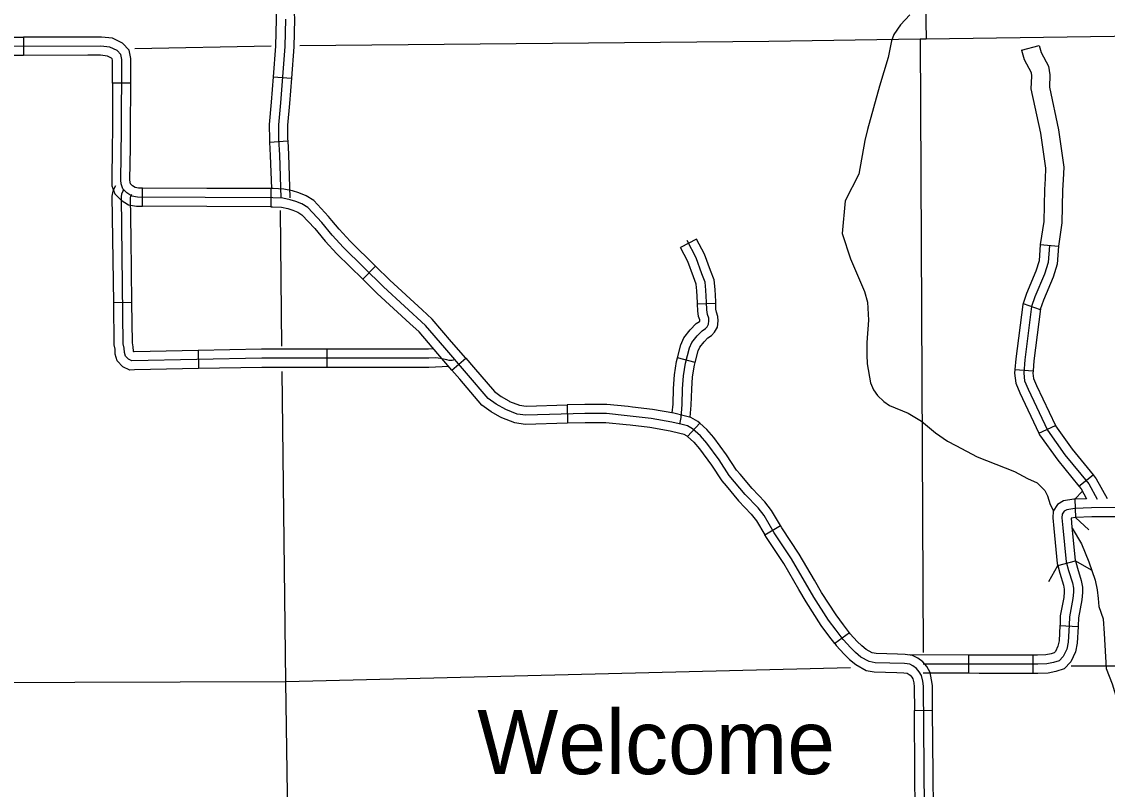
# Model space of a CAD drawing. Extents: x 1373862 to 1376999, y 1168398 to 1170455.
# Drawn here: x 1375095.6 to 1375274.1, y 1169300.7 to 1169426.9 of the extents above; entities that cross this region are included whole.
import ezdxf

# ---------------------------------------------------------------- set-up
doc = ezdxf.new("R2010")
doc.units = 0
for name, color, linetype in [('Level 24', 7, 'Continuous'), ('Level 31', 7, 'Continuous'), ('Level 32', 7, 'Continuous'), ('Level 35', 7, 'Continuous'), ('Level 38', 7, 'Continuous'), ('Level 4', 7, 'Continuous'), ('Level 45', 7, 'Continuous'), ('Level 46', 7, 'Continuous'), ('Level 5', 7, 'Continuous'), ('Level 8', 7, 'Continuous')]:
    doc.layers.add(name, color=color, linetype=linetype)

msp = doc.modelspace()

# ---------------------------------------------------------------- linework, layer by layer
at = {"layer": 'Level 31'}
for p, q in [((1375095.86, 1169424.33), (1375095.87, 1169421.33)), ((1375113.49, 1169416.76), (1375110.49, 1169416.77)), ((1375115.42, 1169396.52), (1375115.43, 1169399.52)), ((1375136.55, 1169399.43), (1375136.54, 1169396.43)), ((1375144.27, 1169392.26), (1375144.27, 1169392.26)), ((1375151.65, 1169384.52), (1375153.75, 1169386.65)), ((1375166.33, 1169369.55), (1375168.6, 1169371.52)), ((1375175.68, 1169364.52), (1375175.68, 1169364.52)), ((1375185.27, 1169363.85), (1375185.36, 1169360.85)), ((1375207.09, 1169360.88), (1375205.07, 1169358.67)), ((1375211.43, 1169350.53), (1375211.43, 1169350.53)), ((1375217.81, 1169342.49), (1375220.4, 1169344.01)), ((1375231.72, 1169326.4), (1375229.32, 1169324.6)), ((1375242.4, 1169313.62), (1375245.4, 1169313.64))]:
    msp.add_line(p, q, dxfattribs=at)
for points in [[(1375085.3, 1169424.31), (1375095.86, 1169424.33)], [(1375106.42, 1169424.35), (1375095.86, 1169424.33)], [(1375113.49, 1169416.76), (1375113.5, 1169420.82), (1375113.24, 1169422.18), (1375112.13, 1169423.35), (1375110.5, 1169424.14), (1375108.68, 1169424.35), (1375106.42, 1169424.35)], [(1375244.04, 1169297.38), (1375243.87, 1169317.61), (1375243.76, 1169318.42), (1375243.56, 1169319.34), (1375243.2, 1169319.97), (1375242.75, 1169320.51), (1375242.15, 1169320.94), (1375241.65, 1169321.2), (1375240.76, 1169321.31), (1375235.95, 1169321.47), (1375234.97, 1169321.64), (1375233.59, 1169322.4), (1375232.73, 1169323.12), (1375231.93, 1169323.91), (1375230.69, 1169325.28), (1375229.54, 1169326.81), (1375228.29, 1169328.46), (1375225.85, 1169332.23), (1375222.19, 1169338.55), (1375219.34, 1169342.85), (1375217.68, 1169345.67), (1375216.69, 1169346.91), (1375214.58, 1169349.11), (1375211.95, 1169352.25), (1375210.26, 1169354.81), (1375208.23, 1169357.55), (1375207.19, 1169358.76), (1375205.92, 1169359.92), (1375205.07, 1169360.4), (1375204.2, 1169360.63), (1375202.5, 1169361.02), (1375199.12, 1169361.61), (1375195.17, 1169362.09), (1375191.73, 1169362.43), (1375188.2, 1169362.43), (1375178.47, 1169362.15), (1375177.03, 1169362.35), (1375175.17, 1169363.08), (1375173.62, 1169363.96), (1375172.29, 1169364.94), (1375168.74, 1169369.06), (1375165.13, 1169373.24), (1375161.99, 1169376.94), (1375155.06, 1169383.26), (1375148.48, 1169389.75), (1375146.62, 1169391.78), (1375144.9, 1169393.84), (1375142.62, 1169396.3), (1375141.66, 1169396.92), (1375140.67, 1169397.31), (1375139.71, 1169397.59), (1375138.5, 1169397.85), (1375136.86, 1169397.93), (1375114.6, 1169398.02), (1375113.67, 1169398.19), (1375112.85, 1169398.72), (1375112.17, 1169399.4), (1375111.89, 1169400.19), (1375111.86, 1169400.84), (1375111.97, 1169409.09), (1375112, 1169420.68), (1375111.85, 1169421.47), (1375111.23, 1169422.12), (1375110.07, 1169422.68), (1375108.59, 1169422.85), (1375061.33, 1169422.76)], [(1375095.87, 1169421.33), (1375085.31, 1169421.31)], [(1375106.43, 1169421.35), (1375095.87, 1169421.33)], [(1375110.49, 1169416.77), (1375110.5, 1169420.54), (1375110.46, 1169420.75), (1375110.33, 1169420.88), (1375109.64, 1169421.22), (1375108.5, 1169421.35), (1375106.43, 1169421.35)], [(1375110.49, 1169416.77), (1375110.47, 1169409.11), (1375110.43, 1169406.22)], [(1375113.43, 1169406.18), (1375113.47, 1169409.08), (1375113.49, 1169416.76)], [(1375110.43, 1169406.22), (1375110.36, 1169400.82), (1375110.4, 1169399.9), (1375110.87, 1169398.58), (1375111.9, 1169397.55), (1375113.1, 1169396.77), (1375114.46, 1169396.52), (1375115.42, 1169396.52)], [(1375115.43, 1169399.52), (1375114.74, 1169399.52), (1375114.23, 1169399.61), (1375113.8, 1169399.89), (1375113.47, 1169400.22), (1375113.38, 1169400.48), (1375113.36, 1169400.86), (1375113.43, 1169406.18)], [(1375125.99, 1169399.47), (1375115.43, 1169399.52)], [(1375136.55, 1169399.43), (1375125.99, 1169399.47)], [(1375146.57, 1169394.19), (1375146.03, 1169394.83), (1375143.59, 1169397.45), (1375142.35, 1169398.26), (1375141.16, 1169398.73), (1375140.08, 1169399.05), (1375138.69, 1169399.34), (1375136.9, 1169399.43), (1375136.55, 1169399.43)], [(1375125.98, 1169396.47), (1375115.42, 1169396.52)], [(1375136.54, 1169396.43), (1375125.98, 1169396.47)], [(1375136.54, 1169396.43), (1375136.82, 1169396.43), (1375138.31, 1169396.36), (1375139.35, 1169396.14), (1375140.18, 1169395.89), (1375140.97, 1169395.58), (1375141.65, 1169395.14), (1375143.78, 1169392.85), (1375144.27, 1169392.26)], [(1375153.75, 1169386.65), (1375149.56, 1169390.79), (1375147.75, 1169392.77), (1375146.57, 1169394.19)], [(1375144.27, 1169392.26), (1375145.49, 1169390.79), (1375147.4, 1169388.71), (1375151.65, 1169384.52)], [(1375161.42, 1169379.49), (1375156.09, 1169384.35), (1375153.75, 1169386.65)], [(1375159.4, 1169377.27), (1375154.02, 1169382.17), (1375151.65, 1169384.52)], [(1375168.6, 1169371.52), (1375166.26, 1169374.22), (1375163.08, 1169377.98), (1375161.42, 1169379.49)], [(1375166.33, 1169369.55), (1375163.99, 1169372.27), (1375160.91, 1169375.89), (1375159.4, 1169377.27)], [(1375168.6, 1169371.52), (1375169.87, 1169370.05), (1375173.32, 1169366.05), (1375174.44, 1169365.22), (1375175.68, 1169364.52)], [(1375174.21, 1169361.9), (1375172.8, 1169362.7), (1375171.26, 1169363.84), (1375167.6, 1169368.08), (1375166.33, 1169369.55)], [(1375175.68, 1169364.52), (1375175.82, 1169364.44), (1375177.42, 1169363.81), (1375178.55, 1169363.65), (1375185.27, 1169363.85)], [(1375196.03, 1169363.5), (1375195.33, 1169363.59), (1375191.8, 1169363.93), (1375188.18, 1169363.93), (1375185.27, 1169363.85)], [(1375207.09, 1169360.88), (1375206.8, 1169361.14), (1375205.64, 1169361.8), (1375204.55, 1169362.08), (1375202.8, 1169362.49), (1375199.34, 1169363.1), (1375196.03, 1169363.5)], [(1375185.36, 1169360.85), (1375178.39, 1169360.65), (1375176.65, 1169360.89), (1375174.53, 1169361.72), (1375174.21, 1169361.9)], [(1375195.67, 1169360.52), (1375195.01, 1169360.6), (1375191.65, 1169360.93), (1375188.22, 1169360.93), (1375185.36, 1169360.85)], [(1375205.07, 1169358.67), (1375205.03, 1169358.7), (1375204.5, 1169359), (1375203.84, 1169359.17), (1375202.2, 1169359.55), (1375198.9, 1169360.13), (1375195.67, 1169360.52)], [(1375213.73, 1169352.46), (1375213.16, 1169353.14), (1375211.49, 1169355.67), (1375209.4, 1169358.49), (1375208.26, 1169359.81), (1375207.09, 1169360.88)], [(1375205.07, 1169358.67), (1375206.11, 1169357.72), (1375207.06, 1169356.61), (1375209.03, 1169353.95), (1375210.75, 1169351.35), (1375211.43, 1169350.53)], [(1375220.4, 1169344.01), (1375218.92, 1169346.52), (1375217.82, 1169347.9), (1375215.69, 1169350.12), (1375213.73, 1169352.46)], [(1375211.43, 1169350.53), (1375213.46, 1169348.11), (1375215.56, 1169345.92), (1375216.44, 1169344.82), (1375217.81, 1169342.49)], [(1375225.97, 1169335.03), (1375223.46, 1169339.34), (1375220.61, 1169343.64), (1375220.4, 1169344.01)], [(1375223.37, 1169333.52), (1375220.91, 1169337.76), (1375218.07, 1169342.05), (1375217.81, 1169342.49)], [(1375231.72, 1169326.4), (1375230.74, 1169327.71), (1375229.52, 1169329.32), (1375227.13, 1169333.01), (1375225.97, 1169335.03)], [(1375229.32, 1169324.6), (1375228.34, 1169325.91), (1375227.06, 1169327.6), (1375224.58, 1169331.45), (1375223.37, 1169333.52)], [(1375239.61, 1169322.85), (1375236.1, 1169322.96), (1375235.48, 1169323.07), (1375234.44, 1169323.64), (1375233.74, 1169324.23), (1375233.01, 1169324.95), (1375231.85, 1169326.23), (1375231.72, 1169326.4)], [(1375229.32, 1169324.6), (1375229.53, 1169324.32), (1375230.85, 1169322.87), (1375231.72, 1169322.01), (1375232.74, 1169321.15), (1375234.47, 1169320.2), (1375235.79, 1169319.97), (1375239.52, 1169319.85)], [(1375245.4, 1169313.64), (1375245.37, 1169317.71), (1375245.24, 1169318.67), (1375244.98, 1169319.88), (1375244.43, 1169320.84), (1375243.78, 1169321.61), (1375242.94, 1169322.23), (1375242.09, 1169322.65), (1375240.88, 1169322.81), (1375239.61, 1169322.85)], [(1375239.52, 1169319.85), (1375240.64, 1169319.81), (1375241.2, 1169319.74), (1375241.37, 1169319.66), (1375241.71, 1169319.41), (1375241.96, 1169319.11), (1375242.15, 1169318.79), (1375242.28, 1169318.16), (1375242.37, 1169317.5), (1375242.4, 1169313.62)], [(1375242.49, 1169303.06), (1375242.4, 1169313.62)], [(1375245.49, 1169303.08), (1375245.4, 1169313.64)], [(1375242.54, 1169292.51), (1375242.54, 1169297.37), (1375242.49, 1169303.06)], [(1375245.54, 1169292.51), (1375245.54, 1169297.39), (1375245.49, 1169303.08)]]:
    msp.add_lwpolyline(points, dxfattribs=at)
at = {"layer": 'Level 32'}
for p, q in [((1375136.93, 1169417.82), (1375139.92, 1169417.59)), ((1375136.32, 1169407.08), (1375139.32, 1169407.26)), ((1375206.58, 1169391.13), (1375203.92, 1169389.74)), ((1375263.11, 1169390.22), (1375266.1, 1169389.99)), ((1375209.73, 1169380.51), (1375206.73, 1169380.41)), ((1375260.27, 1169380.53), (1375263.11, 1169379.56)), ((1375206.32, 1169370.82), (1375203.42, 1169371.59)), ((1375258.93, 1169369.68), (1375261.93, 1169369.44)), ((1375262.87, 1169359.19), (1375265.59, 1169360.46)), ((1375269.45, 1169350.49), (1375271.78, 1169352.38)), ((1375268.79, 1169348.35), (1375268.88, 1169345.35)), ((1375265.99, 1169337.45), (1375268.88, 1169338.24)), ((1375266.35, 1169327.59), (1375269.34, 1169327.4)), ((1375251.31, 1169322.72), (1375251.3, 1169319.72)), ((1375261.87, 1169322.71), (1375261.87, 1169319.71))]:
    msp.add_line(p, q, dxfattribs=at)
for points in [[(1375137.39, 1169428.2), (1375137.42, 1169427.3), (1375137.31, 1169422.87), (1375136.93, 1169417.82)], [(1375138.92, 1169427.3), (1375138.81, 1169422.79), (1375138.1, 1169413.53), (1375137.77, 1169409.9), (1375137.8, 1169407.5), (1375137.95, 1169404.96), (1375138.17, 1169397.87)], [(1375140.39, 1169428.29), (1375140.42, 1169427.31), (1375140.31, 1169422.72), (1375139.92, 1169417.59)], [(1375136.93, 1169417.82), (1375136.61, 1169413.65), (1375136.26, 1169409.96), (1375136.3, 1169407.44), (1375136.32, 1169407.08)], [(1375139.92, 1169417.59), (1375139.6, 1169413.4), (1375139.27, 1169409.85), (1375139.3, 1169407.55), (1375139.32, 1169407.26)], [(1375136.32, 1169407.08), (1375136.45, 1169404.89), (1375136.62, 1169399.43)], [(1375139.32, 1169407.26), (1375139.45, 1169405.03), (1375139.67, 1169397.91)], [(1375203.82, 1169360.72), (1375204.03, 1169361.81), (1375204.19, 1169363.91), (1375204.27, 1169366.5), (1375204.43, 1169368.66), (1375204.73, 1169370.7), (1375205.41, 1169373.26), (1375205.79, 1169374.12), (1375206.66, 1169375.2), (1375207.48, 1169376.05), (1375208.05, 1169376.4), (1375208.29, 1169376.69), (1375208.55, 1169377.13), (1375208.6, 1169377.7), (1375208.57, 1169378.12), (1375208.38, 1169378.75), (1375208.27, 1169379.48), (1375208.22, 1169380.77), (1375208.11, 1169382.73), (1375207.98, 1169384.07), (1375207.45, 1169385.44), (1375206.51, 1169388.03), (1375205, 1169390.92)], [(1375206.73, 1169380.41), (1375206.72, 1169380.7), (1375206.62, 1169382.61), (1375206.51, 1169383.72), (1375206.05, 1169384.91), (1375205.14, 1169387.42), (1375203.92, 1169389.74)], [(1375209.73, 1169380.51), (1375209.72, 1169380.84), (1375209.61, 1169382.84), (1375209.45, 1169384.42), (1375208.86, 1169385.96), (1375207.89, 1169388.63), (1375206.58, 1169391.13)], [(1375263.11, 1169390.22), (1375262.9, 1169387.57), (1375262.4, 1169385.87), (1375260.83, 1169382.17), (1375260.27, 1169380.53)], [(1375264.6, 1169390.1), (1375264.38, 1169387.29), (1375263.81, 1169385.36), (1375262.23, 1169381.63), (1375261.69, 1169380.02), (1375260.57, 1169371.27), (1375260.39, 1169369.07), (1375260.52, 1169367.8), (1375261.14, 1169366.44), (1375264.3, 1169359.68), (1375267.16, 1169355.67), (1375271.07, 1169350.88), (1375272.45, 1169348.38)], [(1375266.1, 1169389.99), (1375265.87, 1169387.02), (1375265.23, 1169384.86), (1375263.64, 1169381.1), (1375263.11, 1169379.56)], [(1375203.42, 1169371.59), (1375203.99, 1169373.76), (1375204.49, 1169374.91), (1375205.54, 1169376.19), (1375206.52, 1169377.23), (1375207.06, 1169377.56), (1375207.06, 1169377.57), (1375207.08, 1169377.6), (1375207.09, 1169377.72), (1375207.09, 1169377.85), (1375206.91, 1169378.42), (1375206.77, 1169379.34), (1375206.73, 1169380.41)], [(1375206.32, 1169370.82), (1375206.84, 1169372.77), (1375207.08, 1169373.33), (1375207.79, 1169374.21), (1375208.43, 1169374.88), (1375209.04, 1169375.25), (1375209.51, 1169375.81), (1375210.02, 1169376.66), (1375210.1, 1169377.68), (1375210.06, 1169378.38), (1375209.84, 1169379.09), (1375209.76, 1169379.62), (1375209.73, 1169380.51)], [(1375260.27, 1169380.53), (1375260.22, 1169380.36), (1375259.07, 1169371.42), (1375258.93, 1169369.68)], [(1375263.15, 1169379.68), (1375262.06, 1169371.11), (1375261.93, 1169369.44)], [(1375202.58, 1169362.53), (1375202.69, 1169363.99), (1375202.78, 1169366.58), (1375202.94, 1169368.82), (1375203.26, 1169371), (1375203.42, 1169371.59)], [(1375205.54, 1169361.83), (1375205.68, 1169363.83), (1375205.77, 1169366.43), (1375205.92, 1169368.49), (1375206.21, 1169370.39), (1375206.32, 1169370.82)], [(1375258.93, 1169369.68), (1375258.88, 1169369.06), (1375259.06, 1169367.41), (1375259.77, 1169365.82), (1375262.87, 1169359.19)], [(1375261.93, 1169369.44), (1375261.9, 1169369.09), (1375261.99, 1169368.2), (1375262.5, 1169367.07), (1375265.59, 1169360.46)], [(1375262.87, 1169359.19), (1375262.99, 1169358.92), (1375265.97, 1169354.76), (1375269.45, 1169350.49)], [(1375265.59, 1169360.46), (1375265.6, 1169360.44), (1375268.35, 1169356.58), (1375271.78, 1169352.38)], [(1375271.78, 1169352.38), (1375272.31, 1169351.72), (1375274.13, 1169348.45)], [(1375269.45, 1169350.49), (1375269.82, 1169350.04), (1375270.72, 1169348.41)], [(1375286.24, 1169347.02), (1375271.54, 1169346.93), (1375268.78, 1169346.85), (1375267.46, 1169346.63), (1375267.02, 1169346.36), (1375266.71, 1169345.88), (1375266.67, 1169345.31), (1375266.8, 1169343.64), (1375267.37, 1169338.07), (1375267.77, 1169336.62), (1375268.38, 1169334.6), (1375268.56, 1169333.72), (1375268.56, 1169333.06), (1375268.47, 1169332.01), (1375267.9, 1169329.02), (1375267.86, 1169327.62), (1375267.68, 1169324.85), (1375267.46, 1169323.71), (1375266.89, 1169322.48), (1375266.23, 1169321.78), (1375265.27, 1169321.48), (1375264.21, 1169321.26), (1375262.68, 1169321.21), (1375253.07, 1169321.21), (1375243.83, 1169321.24)], [(1375268.79, 1169348.35), (1375268.63, 1169348.34), (1375266.93, 1169348.06), (1375265.95, 1169347.47), (1375265.25, 1169346.37), (1375265.17, 1169345.31), (1375265.31, 1169343.51), (1375265.89, 1169337.79), (1375265.99, 1169337.45)], [(1375270.72, 1169348.41), (1375268.79, 1169348.35)], [(1375268.92, 1169345.35), (1375268.18, 1169345.23), (1375268.3, 1169343.78), (1375268.85, 1169338.34), (1375268.88, 1169338.24)], [(1375279.4, 1169345.48), (1375271.57, 1169345.43), (1375268.88, 1169345.35)], [(1375268.88, 1169338.24), (1375269.21, 1169337.03), (1375269.84, 1169334.97), (1375270.06, 1169333.87), (1375270.06, 1169333), (1375269.96, 1169331.81), (1375269.4, 1169328.86), (1375269.35, 1169327.55), (1375269.34, 1169327.4)], [(1375265.99, 1169337.45), (1375266.33, 1169336.2), (1375266.93, 1169334.23), (1375267.06, 1169333.57), (1375267.06, 1169333.13), (1375266.98, 1169332.21), (1375266.4, 1169329.19), (1375266.36, 1169327.69), (1375266.35, 1169327.59)], [(1375266.35, 1169327.59), (1375266.19, 1169325.04), (1375266.02, 1169324.18), (1375265.63, 1169323.33), (1375265.41, 1169323.09), (1375264.89, 1169322.93), (1375264.04, 1169322.75), (1375262.66, 1169322.71), (1375261.87, 1169322.71)], [(1375269.34, 1169327.4), (1375269.17, 1169324.67), (1375268.9, 1169323.25), (1375268.15, 1169321.63), (1375267.06, 1169320.47), (1375265.65, 1169320.02), (1375264.39, 1169319.76), (1375262.7, 1169319.71), (1375261.87, 1169319.71)], [(1375251.31, 1169322.72), (1375241.54, 1169322.75)], [(1375261.87, 1169322.71), (1375253.07, 1169322.71), (1375251.31, 1169322.72)], [(1375251.3, 1169319.72), (1375243.83, 1169319.74)], [(1375261.87, 1169319.71), (1375253.07, 1169319.71), (1375251.3, 1169319.72)]]:
    msp.add_lwpolyline(points, dxfattribs=at)
at = {"layer": 'Level 35'}
for points in [[(1375241.66, 1169428.01), (1375240.1, 1169426.38), (1375239, 1169424.75), (1375238.63, 1169423.71), (1375238.1, 1169420.97), (1375236.66, 1169416.26), (1375234.67, 1169409.14), (1375234.26, 1169407.35), (1375233.26, 1169401.78), (1375231.01, 1169397.41), (1375230.54, 1169392.02), (1375231.88, 1169387.9), (1375234.18, 1169382.51), (1375234.71, 1169380.78), (1375234.87, 1169377.79), (1375234.56, 1169374.13), (1375234.56, 1169372.08), (1375234.65, 1169370.6), (1375235.18, 1169367.47), (1375235.65, 1169366.34), (1375236.33, 1169365.39), (1375237.38, 1169364.42), (1375238.31, 1169363.74), (1375241.39, 1169362.5), (1375243.58, 1169361.21), (1375245.85, 1169359.29), (1375247.83, 1169357.92), (1375249.19, 1169357.17), (1375252.7, 1169355.32), (1375254.25, 1169354.74)], [(1375254.25, 1169354.74), (1375258.89, 1169352.93), (1375261.01, 1169351.77), (1375262.59, 1169351.03), (1375263.86, 1169349.77), (1375264.29, 1169348.9), (1375264.73, 1169347.46), (1375265.29, 1169346.44)], [(1375268.34, 1169343.59), (1375269.9, 1169341), (1375271.11, 1169338.04), (1375272.15, 1169335.06), (1375272.44, 1169333.45), (1375272.63, 1169332.04), (1375272.76, 1169330.71), (1375273.44, 1169328.67), (1375273.63, 1169326.29), (1375273.94, 1169320.49), (1375274.94, 1169318), (1375276.07, 1169314.23)]]:
    msp.add_lwpolyline(points, dxfattribs=at)
at = {"layer": 'Level 38'}
for points in [[(1375268.79, 1169348.35), (1375270.03, 1169349.66)], [(1375271.07, 1169343.29), (1375268.88, 1169345.35)], [(1375268.88, 1169338.24), (1375271.49, 1169336.75)], [(1375264.5, 1169334.84), (1375265.99, 1169337.45)]]:
    msp.add_lwpolyline(points, dxfattribs=at)
at = {"layer": 'Level 4'}
for points in [[(1375141.28, 1169422.97), (1375218.46, 1169423.68), (1375243.37, 1169424.03), (1375244.34, 1169424.04), (1375348.71, 1169425.54), (1375349.94, 1169425.54), (1375454.46, 1169425.4), (1375455.43, 1169425.4), (1375476.41, 1169425.48)], [(1375114.18, 1169422.44), (1375136.58, 1169422.91)]]:
    msp.add_lwpolyline(points, dxfattribs=at)
at = {"layer": 'Level 45'}
for p, q in [((1375113.68, 1169380.68), (1375110.68, 1169380.64)), ((1375124.6, 1169372.82), (1375124.66, 1169369.82)), ((1375145.75, 1169373.03), (1375145.75, 1169370.03))]:
    msp.add_line(p, q, dxfattribs=at)
for points in [[(1375110.55, 1169391.2), (1375110.46, 1169398.18), (1375110.59, 1169398.98), (1375110.81, 1169399.57), (1375111.02, 1169399.96)], [(1375166.82, 1169371.28), (1375166.36, 1169371.18), (1375165.88, 1169371.18), (1375165.48, 1169371.27), (1375164.47, 1169371.49), (1375163.68, 1169371.58), (1375162.5, 1169371.53), (1375135.03, 1169371.53), (1375113.67, 1169371.1), (1375113.1, 1169371.36), (1375112.62, 1169371.89), (1375112.44, 1169372.46), (1375112.4, 1169373.2), (1375112.27, 1169373.9), (1375111.96, 1169398.07), (1375112.05, 1169398.59), (1375112.18, 1169398.95), (1375112.34, 1169399.24)], [(1375113.55, 1169391.24), (1375113.46, 1169397.95), (1375113.5, 1169398.2), (1375113.54, 1169398.32), (1375113.65, 1169398.52)], [(1375110.68, 1169380.64), (1375110.55, 1169391.2)], [(1375113.68, 1169380.68), (1375113.55, 1169391.24)], [(1375114.1, 1169369.6), (1375113.35, 1169369.59), (1375112.2, 1169370.12), (1375111.28, 1169371.12), (1375110.95, 1169372.19), (1375110.91, 1169373.02), (1375110.77, 1169373.76), (1375110.68, 1169380.64)], [(1375114.04, 1169372.6), (1375113.99, 1169372.6), (1375113.95, 1169372.65), (1375113.93, 1169372.72), (1375113.89, 1169373.39), (1375113.76, 1169374.05), (1375113.68, 1169380.68)], [(1375124.6, 1169372.82), (1375114.04, 1169372.6)], [(1375135.19, 1169373.03), (1375135.02, 1169373.03), (1375124.6, 1169372.82)], [(1375145.75, 1169373.03), (1375135.19, 1169373.03)], [(1375156.31, 1169373.03), (1375145.75, 1169373.03)], [(1375163.31, 1169373.07), (1375162.47, 1169373.03), (1375156.31, 1169373.03)], [(1375135.19, 1169370.03), (1375135.05, 1169370.03), (1375124.66, 1169369.82)], [(1375145.75, 1169370.03), (1375135.19, 1169370.03)], [(1375156.31, 1169370.03), (1375145.75, 1169370.03)], [(1375165.81, 1169370.16), (1375162.53, 1169370.03), (1375156.31, 1169370.03)], [(1375124.66, 1169369.82), (1375114.1, 1169369.6)]]:
    msp.add_lwpolyline(points, dxfattribs=at)
at = {"layer": 'Level 46'}
for points in [[(1375260.04, 1169422.18), (1375262.94, 1169422.94), (1375263.24, 1169421.79), (1375264.46, 1169419.54), (1375264.7, 1169418.12), (1375264.6, 1169416.09), (1375266.12, 1169409.09), (1375266.98, 1169402.93), (1375266.89, 1169400.89), (1375266.78, 1169399.17), (1375266.67, 1169393.78), (1375266.1, 1169389.99)], [(1375260.04, 1169422.18), (1375260.43, 1169420.68), (1375261.59, 1169418.54), (1375261.69, 1169417.94), (1375261.58, 1169415.85), (1375263.17, 1169408.56), (1375263.97, 1169402.79), (1375263.89, 1169401.05), (1375263.78, 1169399.3), (1375263.67, 1169394.03), (1375263.11, 1169390.22)]]:
    msp.add_lwpolyline(points, dxfattribs=at)
at = {"layer": 'Level 5'}
for points in [[(1375242.3, 1169527.75), (1375244.34, 1169424.04)], [(1375243.37, 1169424.03), (1375243.85, 1169323.16)], [(1375231.91, 1169320.65), (1375139, 1169318.31)], [(1375292.58, 1169320.88), (1375268.2, 1169320.91)], [(1375139, 1169318.31), (1375034.76, 1169317.98)]]:
    msp.add_lwpolyline(points, dxfattribs=at)
at = {"layer": 'Level 8'}
for points in [[(1375138.37, 1169373.53), (1375138.12, 1169395.83)], [(1375140.52, 1169215.14), (1375139, 1169318.31), (1375138.42, 1169369.38)]]:
    msp.add_lwpolyline(points, dxfattribs=at)

# ---------------------------------------------------------------- texts
at = {"layer": 'Level 24'}
msp.add_text('Welcome', height=10.56, dxfattribs=at).set_placement((1375170.49, 1169303.14))

doc.saveas('drawing.dxf')
